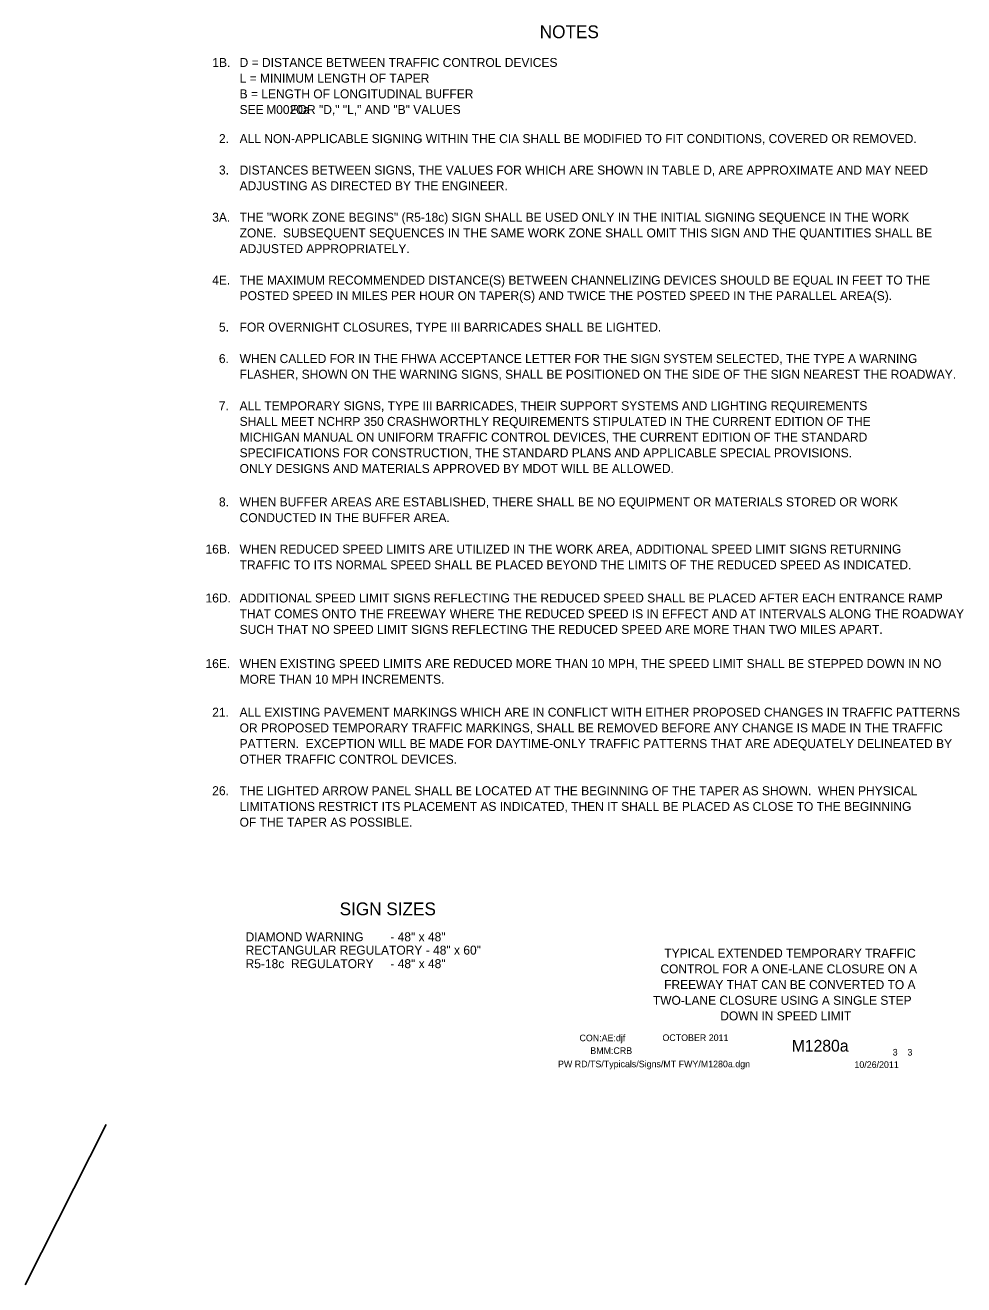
# Model space of a CAD drawing. Extents: x 16590 to 19508, y 5703 to 6974.
# Drawn here: x 18630 to 19508, y 5730 to 6909 of the extents above; entities that cross this region are included whole.
import ezdxf

# ---------------------------------------------------------------- set-up
doc = ezdxf.new("R2010")
doc.units = 0
for name, color, linetype in [('BORDER', 7, 'Continuous'), ('BORDER_SIGNAL_WO', 7, 'Continuous'), ('TYPICAL_TEXT_DIMEN_PR', 7, 'Continuous')]:
    doc.layers.add(name, color=color, linetype=linetype)

msp = doc.modelspace()

# ---------------------------------------------------------------- linework, layer by layer
at = {"layer": 'TYPICAL_TEXT_DIMEN_PR'}
msp.add_line((18705.8, 5880), (18630.1, 5730.1), dxfattribs=at)

# ---------------------------------------------------------------- texts
at = {"layer": 'BORDER'}
for s, p in [('TYPICAL EXTENDED TEMPORARY TRAFFIC', (19228.1, 6036.3)), ('CONTROL FOR A ONE-LANE CLOSURE ON A', (19224.4, 6021.6)), ('FREEWAY THAT CAN BE CONVERTED TO A', (19227.9, 6006.9)), ('TWO-LANE CLOSURE USING A SINGLE STEP ', (19217.4, 5992.2)), ('DOWN IN SPEED LIMIT', (19280.4, 5977.6))]:
    msp.add_text(s, height=8.373, dxfattribs=at).set_placement(p)
at = {"layer": 'BORDER_SIGNAL_WO'}
for s, height, p in [('CON:AE:djf  ', 6.2, (19148.7, 5958.1)), ('    OCTOBER 2011    ', 6.2, (19217.1, 5958.3)), ('    M1280a   ', 11, (19330.9, 5948.4)), ('BMM:CRB   ', 6.2, (19158.8, 5946.2)), (' 3    3 ', 6.2, (19439.4, 5944.7)), ('PW RD/TS/Typicals/Signs/MT FWY/M1280a.dgn      ', 6.2, (19128.6, 5933.7)), ('10/26/2011    ', 6.2, (19405.9, 5933.1))]:
    msp.add_text(s, height=height, dxfattribs=at).set_placement(p)
at = {"layer": 'TYPICAL_TEXT_DIMEN_PR'}
for s, height, p in [('NOTES', 12, (19111.5, 6897)), ('1B.', 8.4, (18805.2, 6870.1)), ('D = DISTANCE BETWEEN TRAFFIC CONTROL DEVICES', 8.4, (18830.7, 6870.1)), ('L = MINIMUM LENGTH OF TAPER', 8.4, (18830.7, 6855.4)), ('B = LENGTH OF LONGITUDINAL BUFFER', 8.4, (18830.7, 6840.7)), ('SEE        FOR "D," "L," AND "B" VALUES', 8.4, (18830.7, 6826)), ('M0020a', 8.4, (18855.6, 6826)), ('2.', 8.4, (18811.4, 6798.8)), ('ALL NON-APPLICABLE SIGNING WITHIN THE CIA SHALL BE MODIFIED TO FIT CONDITIONS, COVERED OR REMOVED.', 8.4, (18830.7, 6798.8)), ('3.', 8.4, (18811.4, 6769.4)), ('DISTANCES BETWEEN SIGNS, THE VALUES FOR WHICH ARE SHOWN IN TABLE D, ARE APPROXIMATE AND MAY NEED', 8.4, (18830.7, 6769.4)), ('ADJUSTING AS DIRECTED BY THE ENGINEER.', 8.4, (18830.7, 6754.7)), ('3A.', 8.4, (18805.1, 6725.2)), ('THE "WORK ZONE BEGINS" (R5-18c) SIGN SHALL BE USED ONLY IN THE INITIAL SIGNING SEQUENCE IN THE WORK', 8.4, (18830.7, 6725.2)), ('ZONE.  SUBSEQUENT SEQUENCES IN THE SAME WORK ZONE SHALL OMIT THIS SIGN AND THE QUANTITIES SHALL BE', 8.4, (18830.7, 6710.5)), ('ADJUSTED APPROPRIATELY.', 8.4, (18830.7, 6695.8)), ('4E.', 8.4, (18805.1, 6666.4)), ('THE MAXIMUM RECOMMENDED DISTANCE(S) BETWEEN CHANNELIZING DEVICES SHOULD BE EQUAL IN FEET TO THE', 8.4, (18830.7, 6666.4)), ('POSTED SPEED IN MILES PER HOUR ON TAPER(S) AND TWICE THE POSTED SPEED IN THE PARALLEL AREA(S).', 8.4, (18830.7, 6651.8)), ('5.', 8.4, (18811.4, 6622.4)), ('FOR OVERNIGHT CLOSURES, TYPE III BARRICADES SHALL BE LIGHTED. ', 8.4, (18830.7, 6622.4)), ('6.', 8.4, (18811.3, 6592.9)), ('WHEN CALLED FOR IN THE FHWA ACCEPTANCE LETTER FOR THE SIGN SYSTEM SELECTED, THE TYPE A WARNING ', 8.4, (18830.7, 6592.9)), ('FLASHER, SHOWN ON THE WARNING SIGNS, SHALL BE POSITIONED ON THE SIDE OF THE SIGN NEAREST THE ROADWAY.', 8.4, (18830.7, 6578.2)), ('7.', 8.4, (18811.3, 6548.8)), ('ALL TEMPORARY SIGNS, TYPE III BARRICADES, THEIR SUPPORT SYSTEMS AND LIGHTING REQUIREMENTS', 8.4, (18830.7, 6548.8)), ('SHALL MEET NCHRP 350 CRASHWORTHLY REQUIREMENTS STIPULATED IN THE CURRENT EDITION OF THE', 8.4, (18830.7, 6534.1)), ('MICHIGAN MANUAL ON UNIFORM TRAFFIC CONTROL DEVICES, THE CURRENT EDITION OF THE STANDARD', 8.4, (18830.7, 6519.4)), ('SPECIFICATIONS FOR CONSTRUCTION, THE STANDARD PLANS AND APPLICABLE SPECIAL PROVISIONS.', 8.4, (18830.7, 6504.7)), ('ONLY DESIGNS AND MATERIALS APPROVED BY MDOT WILL BE ALLOWED.', 8.4, (18830.7, 6490)), ('8.', 8.4, (18811.4, 6458.7)), ('WHEN BUFFER AREAS ARE ESTABLISHED, THERE SHALL BE NO EQUIPMENT OR MATERIALS STORED OR WORK     ', 8.4, (18830.7, 6458.7)), ('CONDUCTED IN THE BUFFER AREA.', 8.4, (18830.7, 6444)), ('16B.', 8.4, (18798.8, 6414.6)), ('WHEN REDUCED SPEED LIMITS ARE UTILIZED IN THE WORK AREA, ADDITIONAL SPEED LIMIT SIGNS RETURNING', 8.4, (18830.7, 6414.6)), ('TRAFFIC TO ITS NORMAL SPEED SHALL BE PLACED BEYOND THE LIMITS OF THE REDUCED SPEED AS INDICATED.', 8.4, (18830.7, 6399.9)), ('16D.', 8.4, (18798.8, 6368.8)), ('ADDITIONAL SPEED LIMIT SIGNS REFLECTING THE REDUCED SPEED SHALL BE PLACED AFTER EACH ENTRANCE RAMP', 8.4, (18830.7, 6368.8)), ('THAT COMES ONTO THE FREEWAY WHERE THE REDUCED SPEED IS IN EFFECT AND AT INTERVALS ALONG THE ROADWAY', 8.4, (18830.7, 6354.1)), ('SUCH THAT NO SPEED LIMIT SIGNS REFLECTING THE REDUCED SPEED ARE MORE THAN TWO MILES APART.', 8.4, (18830.7, 6339.4)), ('16E.', 8.4, (18798.8, 6307.4)), ('WHEN EXISTING SPEED LIMITS ARE REDUCED MORE THAN 10 MPH, THE SPEED LIMIT SHALL BE STEPPED DOWN IN NO', 8.4, (18830.7, 6307.4)), ('MORE THAN 10 MPH INCREMENTS.', 8.4, (18830.7, 6292.7)), ('21.', 8.4, (18805.1, 6261.9)), ('ALL EXISTING PAVEMENT MARKINGS WHICH ARE IN CONFLICT WITH EITHER PROPOSED CHANGES IN TRAFFIC PATTERNS', 8.4, (18830.7, 6261.9)), ('OR PROPOSED TEMPORARY TRAFFIC MARKINGS, SHALL BE REMOVED BEFORE ANY CHANGE IS MADE IN THE TRAFFIC', 8.4, (18830.7, 6247.2)), ('PATTERN.  EXCEPTION WILL BE MADE FOR DAYTIME-ONLY TRAFFIC PATTERNS THAT ARE ADEQUATELY DELINEATED BY', 8.4, (18830.7, 6232.5)), ('OTHER TRAFFIC CONTROL DEVICES.', 8.4, (18830.7, 6217.8)), ('26.', 8.4, (18805.1, 6188.4)), ('THE LIGHTED ARROW PANEL SHALL BE LOCATED AT THE BEGINNING OF THE TAPER AS SHOWN.  WHEN PHYSICAL', 8.4, (18830.7, 6188.4)), ('LIMITATIONS RESTRICT ITS PLACEMENT AS INDICATED, THEN IT SHALL BE PLACED AS CLOSE TO THE BEGINNING', 8.4, (18830.7, 6173.7)), ('OF THE TAPER AS POSSIBLE.', 8.4, (18830.7, 6159)), ('SIGN SIZES', 12, (18924.3, 6076)), ('DIAMOND WARNING        - 48" x 48"', 8.4, (18836.3, 6051.6)), ('RECTANGULAR REGULATORY - 48" x 60"', 8.4, (18836.3, 6039.2)), ('R5-18c  REGULATORY     - 48" x 48"', 8.4, (18836.3, 6026.5))]:
    msp.add_text(s, height=height, dxfattribs=at).set_placement(p)

doc.saveas('drawing.dxf')
